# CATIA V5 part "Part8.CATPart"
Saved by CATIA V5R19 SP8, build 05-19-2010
Part number: Axe
Bounding box of the stored display mesh (mm): x -14.877 to 14.877, y -14.877 to 14.877, z -255 to 195
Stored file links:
  G:\EU_thinkMotion\CFAO_2010\MMS_groupe1\MMS_groupe1\OK\ppiault\piault\piault_cfao\Part8.CATPart
  G:\EU_thinkMotion\CFAO_2010\MMS_groupe1\MMS_groupe1\OK\ppiault\piault\piault_cfao\Part7.CATPart
  D:\Catia\Finaltest.CATProduct
  G:\Catia Projet\CFAO2\Product2.CATProduct
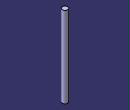
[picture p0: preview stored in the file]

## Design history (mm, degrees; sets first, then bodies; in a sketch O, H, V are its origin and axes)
Parameters
  rayon_axe = 16 mm
  epaisseur = 10 mm
External parameters (linked from other documents)
  External.haut_axe = 195 mm
  External.bas_axe = 255 mm
Body1 (main body)
  Sketch1 on yz-plane, origin (0, 0, 0), H (0, 1, 0), V (0, 0, 1)
    line L1 (-15, 195) -> (0, 195)
    line L2 (0, 195) -> (0, -255)
    line L3 (0, -255) -> (-15, -255)
    line L4 (-15, -255) -> (-15, 195)
    distance L4 L2 = 15
    distance L1 H = 195 {= External.haut_axe}
    distance L3 H = 255 {= External.bas_axe}
    horizontal: L1 H
  Shaft1: profile Sketch1, axis Sketch1.L2, angle 360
